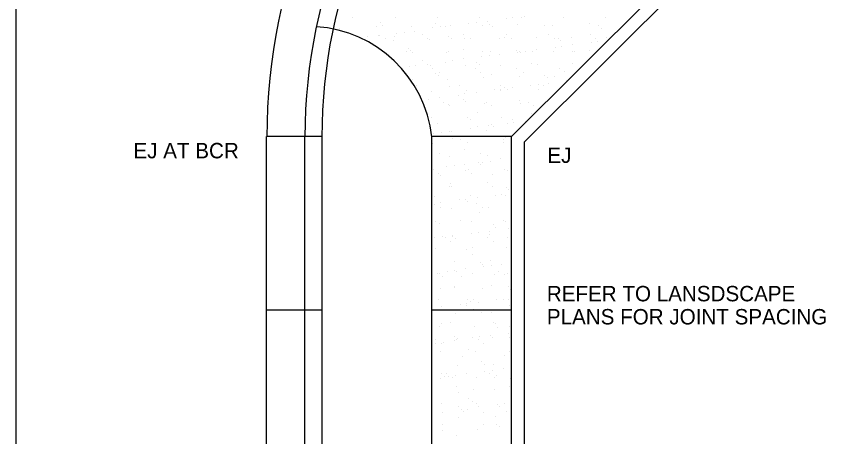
# Model space of a CAD drawing. Extents: x -118779 to -116979, y -104389 to -102939.
# Drawn here: x -118779.4 to -118463.7, y -103368.9 to -103205 of the extents above; entities that cross this region are included whole.
import ezdxf

# ---------------------------------------------------------------- set-up
doc = ezdxf.new("R2010")
doc.units = 0
doc.layers.add('Default', color=7, linetype='Continuous')
doc.layers.add('Misc CnstDet(22)', color=7, linetype='Continuous')

msp = doc.modelspace()

# ---------------------------------------------------------------- linework, layer by layer
at = {"layer": 'Default'}
msp.add_lwpolyline([(-118779.39, -102939.25), (-116979.39, -102939.25), (-116979.39, -104389.25), (-118779.39, -104389.25)], close=True, dxfattribs=at)
at = {"layer": 'Misc CnstDet(22)'}
for p, q in [((-118586.48, -103251.89), (-118457.9, -103123.73)), ((-118648.27, -103205.44), (-118648.27, -103205.44)), ((-118631.68, -103205.44), (-118631.68, -103205.44)), ((-118615.51, -103205.44), (-118615.51, -103205.44)), ((-118598.92, -103205.44), (-118598.92, -103205.44)), ((-118596.01, -103207.1), (-118596.01, -103207.1)), ((-118588.55, -103205.86), (-118588.55, -103205.86)), ((-118586.06, -103205.44), (-118586.06, -103205.44)), ((-118582.74, -103205.44), (-118582.74, -103205.44)), ((-118581.5, -103205.03), (-118581.5, -103205.03)), ((-118566.15, -103205.44), (-118566.15, -103205.44)), ((-118549.98, -103205.44), (-118549.98, -103205.44)), ((-118653.67, -103210), (-118653.67, -103210)), ((-118639.15, -103209.17), (-118639.15, -103209.17)), ((-118637.49, -103207.52), (-118637.49, -103207.52)), ((-118636.66, -103208.76), (-118636.66, -103208.76)), ((-118625.46, -103209.17), (-118625.46, -103209.17)), ((-118617.17, -103209.59), (-118617.17, -103209.59)), ((-118615.92, -103207.93), (-118615.92, -103207.93)), ((-118614.26, -103209.17), (-118614.26, -103209.17)), ((-118612.19, -103209.17), (-118612.19, -103209.17)), ((-118610.12, -103208.76), (-118610.12, -103208.76)), ((-118603.07, -103207.93), (-118603.07, -103207.93)), ((-118600.16, -103207.52), (-118600.16, -103207.52)), ((-118597.67, -103208.76), (-118597.67, -103208.76)), ((-118595.19, -103208.34), (-118595.19, -103208.34)), ((-118593.94, -103209.17), (-118593.94, -103209.17)), ((-118583.99, -103208.34), (-118583.99, -103208.34)), ((-118573.62, -103208.76), (-118573.62, -103208.76)), ((-118570.71, -103208.76), (-118570.71, -103208.76)), ((-118556.2, -103207.93), (-118556.2, -103207.93)), ((-118552.46, -103208.76), (-118552.46, -103208.76)), ((-118551.63, -103210), (-118551.63, -103210)), ((-118542.51, -103207.93), (-118542.51, -103207.93)), ((-118645.37, -103213.32), (-118645.37, -103213.32)), ((-118642.47, -103212.91), (-118642.47, -103212.91)), ((-118638.32, -103212.49), (-118638.32, -103212.49)), ((-118637.91, -103212.49), (-118637.91, -103212.49)), ((-118635.42, -103213.74), (-118635.42, -103213.74)), ((-118632.1, -103212.91), (-118632.1, -103212.91)), ((-118631.27, -103211.66), (-118631.27, -103211.66)), ((-118628.37, -103211.25), (-118628.37, -103211.25)), ((-118624.22, -103210.83), (-118624.22, -103210.83)), ((-118621.32, -103212.08), (-118621.32, -103212.08)), ((-118619.24, -103213.74), (-118619.24, -103213.74)), ((-118610.95, -103212.91), (-118610.95, -103212.91)), ((-118609.7, -103213.74), (-118609.7, -103213.74)), ((-118605.14, -103212.08), (-118605.14, -103212.08)), ((-118604.72, -103213.74), (-118604.72, -103213.74)), ((-118602.65, -103213.74), (-118602.65, -103213.74)), ((-118591.04, -103213.74), (-118591.04, -103213.74)), ((-118589.38, -103213.32), (-118589.38, -103213.32)), ((-118588.55, -103212.08), (-118588.55, -103212.08)), ((-118586.48, -103213.74), (-118586.48, -103213.74)), ((-118576.94, -103213.32), (-118576.94, -103213.32)), ((-118571.96, -103212.08), (-118571.96, -103212.08)), ((-118569.88, -103213.74), (-118569.88, -103213.74)), ((-118568.23, -103213.74), (-118568.23, -103213.74)), ((-118563.25, -103213.32), (-118563.25, -103213.32)), ((-118555.78, -103212.08), (-118555.78, -103212.08)), ((-118553.71, -103213.74), (-118553.71, -103213.74)), ((-118549.56, -103213.32), (-118549.56, -103213.32)), ((-118632.51, -103214.57), (-118632.51, -103214.57)), ((-118618.41, -103214.15), (-118618.41, -103214.15)), ((-118567.4, -103214.57), (-118567.4, -103214.57)), ((-118566.98, -103216.64), (-118566.98, -103216.64)), ((-118562.83, -103216.23), (-118562.83, -103216.23)), ((-118555.37, -103215.4), (-118555.37, -103215.4)), ((-118552.88, -103214.98), (-118552.88, -103214.98)), ((-118627.54, -103218.71), (-118627.54, -103218.71)), ((-118626.71, -103217.47), (-118626.71, -103217.47)), ((-118625.88, -103218.3), (-118625.88, -103218.3)), ((-118625.05, -103219.13), (-118625.05, -103219.13)), ((-118611.78, -103219.13), (-118611.78, -103219.13)), ((-118610.95, -103218.71), (-118610.95, -103218.71)), ((-118605.14, -103217.88), (-118605.14, -103217.88)), ((-118597.67, -103218.71), (-118597.67, -103218.71)), ((-118594.77, -103218.71), (-118594.77, -103218.71)), ((-118591.04, -103219.96), (-118591.04, -103219.96)), ((-118584.4, -103218.3), (-118584.4, -103218.3)), ((-118583.99, -103219.13), (-118583.99, -103219.13)), ((-118583.57, -103218.71), (-118583.57, -103218.71)), ((-118583.16, -103219.13), (-118583.16, -103219.13)), ((-118581.08, -103218.71), (-118581.08, -103218.71)), ((-118578.18, -103218.71), (-118578.18, -103218.71)), ((-118576.94, -103217.88), (-118576.94, -103217.88)), ((-118570.3, -103218.71), (-118570.3, -103218.71)), ((-118569.47, -103217.05), (-118569.47, -103217.05)), ((-118562.83, -103218.71), (-118562.83, -103218.71)), ((-118562, -103218.71), (-118562, -103218.71)), ((-118556.2, -103218.3), (-118556.2, -103218.3)), ((-118621.32, -103222.45), (-118621.32, -103222.45)), ((-118612.19, -103222.86), (-118612.19, -103222.86)), ((-118609.29, -103222.45), (-118609.29, -103222.45)), ((-118605.14, -103221.62), (-118605.14, -103221.62)), ((-118600.16, -103222.86), (-118600.16, -103222.86)), ((-118598.09, -103220.79), (-118598.09, -103220.79)), ((-118595.19, -103220.37), (-118595.19, -103220.37)), ((-118578.59, -103223.28), (-118578.59, -103223.28)), ((-118562.83, -103223.28), (-118562.83, -103223.28)), ((-118626.29, -103224.52), (-118626.29, -103224.52)), ((-118623.8, -103224.11), (-118623.8, -103224.11)), ((-118619.24, -103223.69), (-118619.24, -103223.69)), ((-118618, -103224.11), (-118618, -103224.11)), ((-118617.17, -103225.35), (-118617.17, -103225.35)), ((-118604.31, -103224.11), (-118604.31, -103224.11)), ((-118600.58, -103225.35), (-118600.58, -103225.35)), ((-118598.92, -103223.69), (-118598.92, -103223.69)), ((-118590.62, -103224.11), (-118590.62, -103224.11)), ((-118584.4, -103225.35), (-118584.4, -103225.35)), ((-118576.52, -103223.69), (-118576.52, -103223.69)), ((-118567.81, -103225.35), (-118567.81, -103225.35)), ((-118625.05, -103229.5), (-118625.05, -103229.5)), ((-118615.92, -103227.42), (-118615.92, -103227.42)), ((-118615.09, -103228.25), (-118615.09, -103228.25)), ((-118614.68, -103227.01), (-118614.68, -103227.01)), ((-118611.36, -103229.5), (-118611.36, -103229.5)), ((-118598.5, -103227.01), (-118598.5, -103227.01)), ((-118597.26, -103229.08), (-118597.26, -103229.08)), ((-118594.36, -103227.84), (-118594.36, -103227.84)), ((-118583.57, -103228.67), (-118583.57, -103228.67)), ((-118581.91, -103227.01), (-118581.91, -103227.01)), ((-118573.62, -103228.25), (-118573.62, -103228.25)), ((-118572.37, -103229.08), (-118572.37, -103229.08)), ((-118569.88, -103228.67), (-118569.88, -103228.67)), ((-118565.74, -103226.59), (-118565.74, -103226.59)), ((-118623.39, -103231.99), (-118623.39, -103231.99)), ((-118610.53, -103232.4), (-118610.53, -103232.4)), ((-118606.8, -103231.99), (-118606.8, -103231.99)), ((-118590.62, -103231.99), (-118590.62, -103231.99)), ((-118579.01, -103231.99), (-118579.01, -103231.99)), ((-118576.11, -103231.57), (-118576.11, -103231.57)), ((-118574.03, -103231.99), (-118574.03, -103231.99)), ((-118571.96, -103231.16), (-118571.96, -103231.16)), ((-118564.91, -103229.91), (-118564.91, -103229.91)), ((-118617.58, -103234.47), (-118617.58, -103234.47)), ((-118607.21, -103235.72), (-118607.21, -103235.72)), ((-118604.72, -103235.3), (-118604.72, -103235.3)), ((-118603.9, -103234.06), (-118603.9, -103234.06)), ((-118600.16, -103234.89), (-118600.16, -103234.89)), ((-118593.11, -103233.65), (-118593.11, -103233.65)), ((-118590.62, -103233.65), (-118590.62, -103233.65)), ((-118590.62, -103234.06), (-118590.62, -103234.06)), ((-118589.38, -103232.82), (-118589.38, -103232.82)), ((-118588.13, -103233.65), (-118588.13, -103233.65)), ((-118586.06, -103232.82), (-118586.06, -103232.82)), ((-118576.11, -103233.65), (-118576.11, -103233.65)), ((-118567.81, -103233.23), (-118567.81, -103233.23)), ((-118618.83, -103237.38), (-118618.83, -103237.38)), ((-118614.68, -103236.55), (-118614.68, -103236.55)), ((-118613.02, -103238.62), (-118613.02, -103238.62)), ((-118605.14, -103237.38), (-118605.14, -103237.38)), ((-118604.31, -103238.21), (-118604.31, -103238.21)), ((-118596.84, -103239.04), (-118596.84, -103239.04)), ((-118596.43, -103238.62), (-118596.43, -103238.62)), ((-118583.57, -103237.79), (-118583.57, -103237.79)), ((-118583.16, -103239.04), (-118583.16, -103239.04)), ((-118579.84, -103238.62), (-118579.84, -103238.62)), ((-118610.95, -103239.45), (-118610.95, -103239.45)), ((-118610.53, -103239.87), (-118610.53, -103239.87)), ((-118594.36, -103239.87), (-118594.36, -103239.87)), ((-118577.77, -103239.87), (-118577.77, -103239.87)), ((-118617.58, -103244.43), (-118617.58, -103244.43)), ((-118603.48, -103244.43), (-118603.48, -103244.43)), ((-118602.65, -103245.26), (-118602.65, -103245.26)), ((-118599.75, -103242.36), (-118599.75, -103242.36)), ((-118590.21, -103244.43), (-118590.21, -103244.43)), ((-118586.06, -103245.26), (-118586.06, -103245.26)), ((-118578.59, -103242.77), (-118578.59, -103242.77)), ((-118615.51, -103246.92), (-118615.51, -103246.92)), ((-118599.75, -103248.16), (-118599.75, -103248.16)), ((-118595.6, -103247.75), (-118595.6, -103247.75)), ((-118594.36, -103247.33), (-118594.36, -103247.33)), ((-118593.53, -103248.16), (-118593.53, -103248.16)), ((-118588.13, -103246.92), (-118588.13, -103246.92)), ((-118585.65, -103246.5), (-118585.65, -103246.5)), ((-118581.08, -103246.09), (-118581.08, -103246.09)), ((-118616.75, -103250.65), (-118616.75, -103250.65)), ((-118613.85, -103250.24), (-118613.85, -103250.24)), ((-118610.53, -103249.82), (-118610.53, -103249.82)), ((-118609.7, -103249.82), (-118609.7, -103249.82)), ((-118602.65, -103248.58), (-118602.65, -103248.58)), ((-118596.43, -103249.41), (-118596.43, -103249.41)), ((-118660.3, -103251.89), (-118681.87, -103251.89)), ((-118586.48, -103251.89), (-118617.58, -103251.89)), ((-118617.17, -103254.8), (-118617.17, -103254.8)), ((-118610.12, -103251.89), (-118610.12, -103251.89)), ((-118609.29, -103252.72), (-118609.29, -103252.72)), ((-118608.46, -103251.89), (-118608.46, -103251.89)), ((-118606.38, -103253.14), (-118606.38, -103253.14)), ((-118603.48, -103254.38), (-118603.48, -103254.38)), ((-118592.28, -103251.89), (-118592.28, -103251.89)), ((-118589.79, -103253.14), (-118589.79, -103253.14)), ((-118589.79, -103254.38), (-118589.79, -103254.38)), ((-118588.96, -103252.31), (-118588.96, -103252.31)), ((-118604.72, -103256.87), (-118604.72, -103256.87)), ((-118614.68, -103258.53), (-118614.68, -103258.53)), ((-118610.53, -103259.78), (-118610.53, -103259.78)), ((-118598.5, -103258.53), (-118598.5, -103258.53)), ((-118596.01, -103259.36), (-118596.01, -103259.36)), ((-118590.62, -103260.61), (-118590.62, -103260.61)), ((-118611.78, -103263.51), (-118611.78, -103263.51)), ((-118608.87, -103263.09), (-118608.87, -103263.09)), ((-118604.72, -103262.68), (-118604.72, -103262.68)), ((-118599.33, -103261.85), (-118599.33, -103261.85)), ((-118598.5, -103262.68), (-118598.5, -103262.68)), ((-118597.67, -103261.85), (-118597.67, -103261.85)), ((-118594.77, -103261.43), (-118594.77, -103261.43)), ((-118616.75, -103264.75), (-118616.75, -103264.75)), ((-118615.09, -103266.41), (-118615.09, -103266.41)), ((-118614.26, -103267.24), (-118614.26, -103267.24)), ((-118604.31, -103265.17), (-118604.31, -103265.17)), ((-118603.07, -103264.75), (-118603.07, -103264.75)), ((-118602.24, -103266.41), (-118602.24, -103266.41)), ((-118593.94, -103266.83), (-118593.94, -103266.83)), ((-118589.38, -103264.75), (-118589.38, -103264.75)), ((-118588.13, -103265.17), (-118588.13, -103265.17)), ((-118610.12, -103270.14), (-118610.12, -103270.14)), ((-118596.01, -103269.73), (-118596.01, -103269.73)), ((-118610.53, -103271.39), (-118610.53, -103271.39)), ((-118609.7, -103271.39), (-118609.7, -103271.39)), ((-118593.94, -103271.39), (-118593.94, -103271.39)), ((-118588.55, -103271.8), (-118588.55, -103271.8)), ((-118587.72, -103272.63), (-118587.72, -103272.63)), ((-118616.34, -103275.12), (-118616.34, -103275.12)), ((-118606.8, -103276.37), (-118606.8, -103276.37)), ((-118604.31, -103276.37), (-118604.31, -103276.37)), ((-118604.31, -103276.37), (-118604.31, -103276.37)), ((-118602.65, -103274.71), (-118602.65, -103274.71)), ((-118599.75, -103275.54), (-118599.75, -103275.54)), ((-118592.7, -103274.71), (-118592.7, -103274.71)), ((-118590.21, -103274.29), (-118590.21, -103274.29)), ((-118588.96, -103274.71), (-118588.96, -103274.71)), ((-118616.34, -103278.44), (-118616.34, -103278.44)), ((-118614.26, -103277.61), (-118614.26, -103277.61)), ((-118614.26, -103279.68), (-118614.26, -103279.68)), ((-118609.7, -103280.1), (-118609.7, -103280.1)), ((-118603.48, -103277.2), (-118603.48, -103277.2)), ((-118600.16, -103278.03), (-118600.16, -103278.03)), ((-118597.67, -103279.68), (-118597.67, -103279.68)), ((-118595.6, -103279.68), (-118595.6, -103279.68)), ((-118598.92, -103281.34), (-118598.92, -103281.34)), ((-118615.92, -103285.08), (-118615.92, -103285.08)), ((-118614.68, -103285.91), (-118614.68, -103285.91)), ((-118606.38, -103284.66), (-118606.38, -103284.66)), ((-118602.24, -103285.08), (-118602.24, -103285.08)), ((-118593.53, -103286.32), (-118593.53, -103286.32)), ((-118589.79, -103284.66), (-118589.79, -103284.66)), ((-118588.96, -103285.08), (-118588.96, -103285.08)), ((-118599.33, -103289.22), (-118599.33, -103289.22)), ((-118595.19, -103288.81), (-118595.19, -103288.81)), ((-118592.7, -103287.15), (-118592.7, -103287.15)), ((-118587.72, -103287.56), (-118587.72, -103287.56)), ((-118616.34, -103291.3), (-118616.34, -103291.3)), ((-118613.43, -103290.88), (-118613.43, -103290.88)), ((-118612.19, -103291.3), (-118612.19, -103291.3)), ((-118609.29, -103290.47), (-118609.29, -103290.47)), ((-118609.29, -103290.47), (-118609.29, -103290.47)), ((-118609.29, -103290.88), (-118609.29, -103290.88)), ((-118608.46, -103291.71), (-118608.46, -103291.71)), ((-118602.24, -103289.64), (-118602.24, -103289.64)), ((-118596.01, -103291.3), (-118596.01, -103291.3)), ((-118595.19, -103290.05), (-118595.19, -103290.05)), ((-118588.13, -103291.3), (-118588.13, -103291.3)), ((-118615.92, -103295.45), (-118615.92, -103295.45)), ((-118610.12, -103292.96), (-118610.12, -103292.96)), ((-118603.9, -103295.86), (-118603.9, -103295.86)), ((-118601.82, -103295.03), (-118601.82, -103295.03)), ((-118593.53, -103292.96), (-118593.53, -103292.96)), ((-118588.55, -103295.03), (-118588.55, -103295.03)), ((-118601.82, -103297.93), (-118601.82, -103297.93)), ((-118608.87, -103300.42), (-118608.87, -103300.42)), ((-118598.5, -103300.84), (-118598.5, -103300.84)), ((-118597.67, -103301.67), (-118597.67, -103301.67)), ((-118594.77, -103300.01), (-118594.77, -103300.01)), ((-118594.36, -103302.08), (-118594.36, -103302.08)), ((-118590.21, -103301.67), (-118590.21, -103301.67)), ((-118611.36, -103304.57), (-118611.36, -103304.57)), ((-118608.87, -103304.16), (-118608.87, -103304.16)), ((-118608.04, -103304.57), (-118608.04, -103304.57)), ((-118604.31, -103303.33), (-118604.31, -103303.33)), ((-118597.26, -103302.5), (-118597.26, -103302.5)), ((-118591.45, -103304.57), (-118591.45, -103304.57)), ((-118615.51, -103305.4), (-118615.51, -103305.4)), ((-118614.68, -103305.4), (-118614.68, -103305.4)), ((-118613.43, -103306.23), (-118613.43, -103306.23)), ((-118605.97, -103306.23), (-118605.97, -103306.23)), ((-118601.82, -103305.4), (-118601.82, -103305.4)), ((-118593.11, -103305.81), (-118593.11, -103305.81)), ((-118589.38, -103305.81), (-118589.38, -103305.81)), ((-118588.13, -103305.4), (-118588.13, -103305.4)), ((-118614.26, -103311.21), (-118614.26, -103311.21)), ((-118608.87, -103310.38), (-118608.87, -103310.38)), ((-118608.87, -103310.79), (-118608.87, -103310.79)), ((-118597.67, -103311.21), (-118597.67, -103311.21)), ((-118594.36, -103309.96), (-118594.36, -103309.96)), ((-118587.72, -103310.38), (-118587.72, -103310.38)), ((-118586.89, -103311.62), (-118586.89, -103311.62)), ((-118615.09, -103315.35), (-118615.09, -103315.35)), ((-118606.38, -103317.43), (-118606.38, -103317.43)), ((-118603.9, -103317.01), (-118603.9, -103317.01)), ((-118603.9, -103317.84), (-118603.9, -103317.84)), ((-118603.48, -103315.35), (-118603.48, -103315.35)), ((-118602.65, -103316.18), (-118602.65, -103316.18)), ((-118601.41, -103315.35), (-118601.41, -103315.35)), ((-118599.33, -103316.6), (-118599.33, -103316.6)), ((-118592.28, -103315.35), (-118592.28, -103315.35)), ((-118589.79, -103315.35), (-118589.79, -103315.35)), ((-118587.72, -103315.35), (-118587.72, -103315.35)), ((-118587.3, -103317.84), (-118587.3, -103317.84)), ((-118660.3, -103319.5), (-118681.87, -103319.5)), ((-118586.48, -103319.5), (-118617.58, -103319.5)), ((-118613.85, -103318.26), (-118613.85, -103318.26)), ((-118608.46, -103320.75), (-118608.46, -103320.75)), ((-118601.41, -103319.09), (-118601.41, -103319.09)), ((-118598.09, -103320.33), (-118598.09, -103320.33)), ((-118594.36, -103320.33), (-118594.36, -103320.33)), ((-118614.68, -103325.72), (-118614.68, -103325.72)), ((-118613.85, -103324.89), (-118613.85, -103324.89)), ((-118610.12, -103324.48), (-118610.12, -103324.48)), ((-118600.99, -103325.72), (-118600.99, -103325.72)), ((-118593.53, -103324.48), (-118593.53, -103324.48)), ((-118592.7, -103324.89), (-118592.7, -103324.89)), ((-118591.87, -103326.14), (-118591.87, -103326.14)), ((-118587.3, -103325.72), (-118587.3, -103325.72)), ((-118608.87, -103329.87), (-118608.87, -103329.87)), ((-118601.82, -103330.29), (-118601.82, -103330.29)), ((-118598.92, -103329.87), (-118598.92, -103329.87)), ((-118594.77, -103329.46), (-118594.77, -103329.46)), ((-118593.94, -103330.29), (-118593.94, -103330.29)), ((-118587.72, -103328.63), (-118587.72, -103328.63)), ((-118587.3, -103330.29), (-118587.3, -103330.29)), ((-118615.92, -103331.11), (-118615.92, -103331.11)), ((-118615.92, -103332.36), (-118615.92, -103332.36)), ((-118613.85, -103332.36), (-118613.85, -103332.36)), ((-118613.02, -103331.94), (-118613.02, -103331.94)), ((-118608.87, -103331.53), (-118608.87, -103331.53)), ((-118608.04, -103331.11), (-118608.04, -103331.11)), ((-118607.63, -103330.7), (-118607.63, -103330.7)), ((-118599.33, -103331.11), (-118599.33, -103331.11)), ((-118597.26, -103332.36), (-118597.26, -103332.36)), ((-118614.26, -103335.68), (-118614.26, -103335.68)), ((-118603.07, -103334.85), (-118603.07, -103334.85)), ((-118600.58, -103335.68), (-118600.58, -103335.68)), ((-118587.3, -103335.68), (-118587.3, -103335.68)), ((-118605.55, -103337.75), (-118605.55, -103337.75)), ((-118598.09, -103339.41), (-118598.09, -103339.41)), ((-118589.38, -103337.34), (-118589.38, -103337.34)), ((-118607.63, -103341.07), (-118607.63, -103341.07)), ((-118596.84, -103340.65), (-118596.84, -103340.65)), ((-118593.94, -103343.14), (-118593.94, -103343.14)), ((-118593.53, -103340.65), (-118593.53, -103340.65)), ((-118589.79, -103342.31), (-118589.79, -103342.31)), ((-118614.26, -103346.05), (-118614.26, -103346.05)), ((-118613.85, -103344.39), (-118613.85, -103344.39)), ((-118612.61, -103345.22), (-118612.61, -103345.22)), ((-118611.78, -103344.39), (-118611.78, -103344.39)), ((-118610.95, -103345.22), (-118610.95, -103345.22)), ((-118609.29, -103345.63), (-118609.29, -103345.63)), ((-118608.46, -103344.8), (-118608.46, -103344.8)), ((-118603.9, -103344.39), (-118603.9, -103344.39)), ((-118600.16, -103345.63), (-118600.16, -103345.63)), ((-118596.84, -103343.56), (-118596.84, -103343.56)), ((-118595.19, -103344.39), (-118595.19, -103344.39)), ((-118593.11, -103345.63), (-118593.11, -103345.63)), ((-118592.28, -103344.8), (-118592.28, -103344.8)), ((-118586.89, -103346.05), (-118586.89, -103346.05)), ((-118608.04, -103349.36), (-118608.04, -103349.36)), ((-118587.3, -103349.36), (-118587.3, -103349.36)), ((-118607.21, -103351.44), (-118607.21, -103351.44)), ((-118601.41, -103350.61), (-118601.41, -103350.61)), ((-118593.11, -103350.61), (-118593.11, -103350.61)), ((-118603.07, -103353.93), (-118603.07, -103353.93)), ((-118601.82, -103355.17), (-118601.82, -103355.17)), ((-118613.85, -103356), (-118613.85, -103356)), ((-118607.21, -103357.24), (-118607.21, -103357.24)), ((-118605.97, -103358.07), (-118605.97, -103358.07)), ((-118605.14, -103358.9), (-118605.14, -103358.9)), ((-118603.48, -103358.07), (-118603.48, -103358.07)), ((-118600.16, -103356), (-118600.16, -103356)), ((-118599.33, -103357.24), (-118599.33, -103357.24)), ((-118591.87, -103356.42), (-118591.87, -103356.42)), ((-118591.04, -103357.24), (-118591.04, -103357.24)), ((-118589.38, -103356), (-118589.38, -103356)), ((-118588.55, -103358.9), (-118588.55, -103358.9)), ((-118586.48, -103356), (-118586.48, -103356)), ((-118613.43, -103359.32), (-118613.43, -103359.32)), ((-118607.21, -103361.39), (-118607.21, -103361.39)), ((-118597.26, -103359.32), (-118597.26, -103359.32)), ((-118592.7, -103360.98), (-118592.7, -103360.98)), ((-118613.43, -103363.88), (-118613.43, -103363.88)), ((-118613.43, -103363.88), (-118613.43, -103363.88)), ((-118597.26, -103363.88), (-118597.26, -103363.88)), ((-118592.28, -103363.88), (-118592.28, -103363.88)), ((-118591.04, -103364.71), (-118591.04, -103364.71)), ((-118613.43, -103366.37), (-118613.43, -103366.37)), ((-118608.04, -103368.44), (-118608.04, -103368.44)), ((-118599.75, -103365.96), (-118599.75, -103365.96))]:
    msp.add_line(p, q, dxfattribs=at)
for points in [[(-118581.5, -103791.92), (-118581.5, -103253.97), (-118455.82, -103128.71), (-118400.25, -103128.71)], [(-118681.87, -103791.92), (-118681.87, -103251.89)], [(-118666.94, -103791.92), (-118666.94, -103251.89)], [(-118660.3, -103791.92), (-118660.3, -103251.89)], [(-118617.58, -103791.92), (-118617.58, -103251.89)], [(-118586.48, -103791.92), (-118586.48, -103251.89)]]:
    msp.add_lwpolyline(points, dxfattribs=at)
for centre, radius, start, end in [((-118457.89, -103252.04), 223.87, 90, 180), ((-118457.89, -103252.04), 209.05, 90, 180), ((-118457.89, -103252.04), 202.47, 90, 180), ((-118665.56, -103257.33), 48.29, 6.2941, 86.3572)]:
    msp.add_arc(centre, radius, start, end, dxfattribs=at)

# ---------------------------------------------------------------- texts
for s, p in [('EJ AT BCR', (-118733.73, -103260.38)), ('EJ', (-118572.54, -103262.17)), ('REFER TO LANSDSCAPE', (-118572.74, -103316.09)), ('PLANS FOR JOINT SPACING', (-118572.74, -103325.09))]:
    msp.add_text(s, height=6, dxfattribs=at).set_placement(p)

doc.saveas('drawing.dxf')
